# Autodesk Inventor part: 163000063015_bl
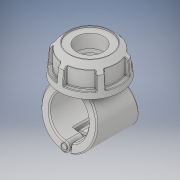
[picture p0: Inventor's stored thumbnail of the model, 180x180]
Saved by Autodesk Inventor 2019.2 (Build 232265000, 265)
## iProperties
Created: 2022-02
Part Number: 163000063015_bl
Material: Generic
Description: Plassadle Threaded 63x1 1/2''
Document SubType Name: Modeling
Designer: comp2
Density: 1 g/cm^3
Appearance: Default
Author: comp2
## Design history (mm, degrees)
derived "16300.ipt"
feature "Solid1::16300.ipt" dims "ScaleForDerivedMember" = 10
feature "Solid2::16300.ipt" dims "ScaleForDerivedMember" = 10
feature "Solid3::16300.ipt" dims "ScaleForDerivedMember" = 10
feature "Solid4::16300.ipt" dims "ScaleForDerivedMember" = 10
tag "TaggingFeature1"
body "Solid1"
body "Solid2"
body "Solid3"
body "Solid4"
other parameters: "d0" = 63 [user parameter], "d2" = 91 [user parameter], "d3" = 31.5 [user parameter], "d7" = 86.45 [user parameter], "d8" = 85 deg [user parameter], "d9" = 45 deg [user parameter], "d10" = 102 [user parameter], "d11" = 49 [user parameter], "d12" = 31.8185 [user parameter], "d13" = 42.84 [user parameter], "d14" = 67.2675 [user parameter], "d42" = 2.8 [user parameter], "d49" = 1.82 [user parameter], "d50" = 89 [user parameter], "d51" = 0 [user parameter], "d52" = 19.6 [user parameter], "d53" = 50.05 [user parameter], "d54" = 31.15 [user parameter], "d55" = 0 [user parameter], "d56" = 17.8 [user parameter], "d57" = 17.8 [user parameter], "d59" = 0 [user parameter], "d60" = 89 [user parameter], "d61" = 0 [user parameter], "d62" = 31.15 [user parameter], "d63" = 0 [user parameter], "d65" = 0 [user parameter], "d67" = 0 [user parameter], "d69" = 0 [user parameter], "d70" = 1 [user parameter], "d71" = 85.44 [user parameter], "d72" = 0 [user parameter], "d73" = 2 [user parameter], "d78" = 86.7 [user parameter], "d79" = 5.1 [user parameter], "d80" = 60 deg [user parameter], "d81" = 5.1 [user parameter], "d84" = 0 [user parameter], "d85" = 1 [user parameter], "d87" = 360 deg [user parameter], "d122" = 49 [user parameter], "d124" = 42.80128 [user parameter], "d125" = 2.27275 [user parameter], "d127" = 136 [user parameter], "d129" = 44.845 [user parameter], "d130" = 38.11825 [user parameter], "d131" = 31.85 [user parameter], "d132" = 45 deg [user parameter], "d133" = 22.295 [user parameter], "d134" = 22.4225 [user parameter], "d136" = 0 [user parameter], "d138" = 0 [user parameter], "d" = 63 [user parameter], "d1" = 25 [user parameter], "B" = 91 [user parameter], "L" = 89 [user parameter], "E_" = 54 [user parameter], "E1" = 102 [user parameter], "H1" = 136 [user parameter], "H2" = 49 [user parameter], "H3" = 78 [user parameter], "H_costum" = 49 [user parameter], "Rp" = 44.845 [user parameter], "d128" = 45.455 [user parameter]
